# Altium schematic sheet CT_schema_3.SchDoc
size 229 x 200 mm
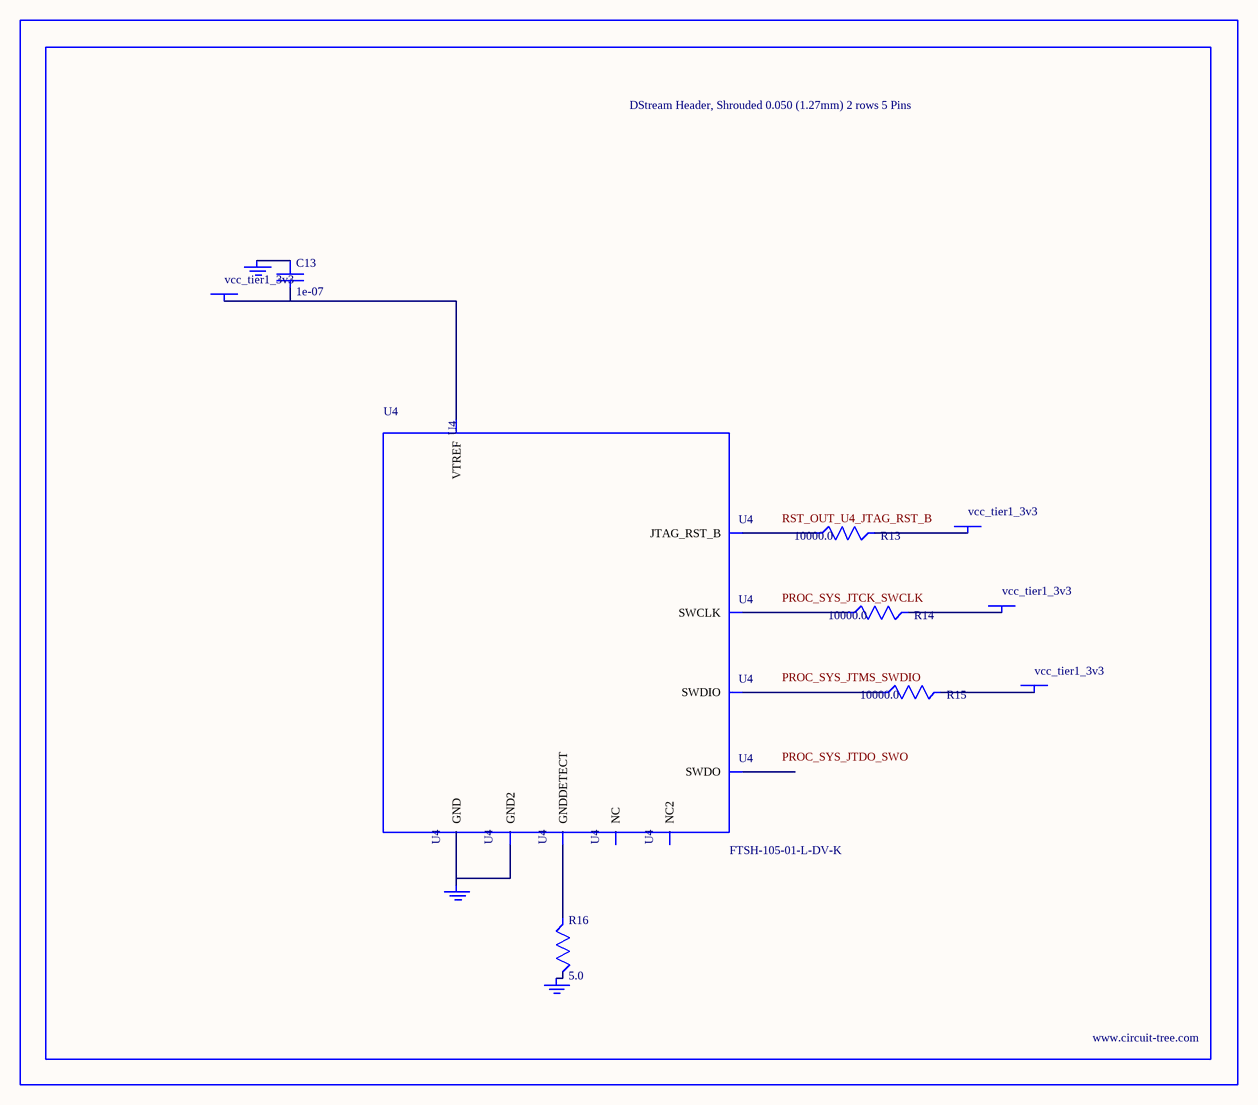
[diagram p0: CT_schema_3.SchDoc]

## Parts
BORDER2  (no value)
C13  1e-07  [C0402]
GND_INSTANCE_2_0  (no value)
GND_INSTANCE_2_1  (no value)
GND_INSTANCE_2_2  (no value)
POWER_INSTANCE_2_0  vcc_tier1_3v3
POWER_INSTANCE_2_1  vcc_tier1_3v3
POWER_INSTANCE_2_2  vcc_tier1_3v3
POWER_INSTANCE_2_3  vcc_tier1_3v3
R13  10000.0  [R0603]
R14  10000.0  [R0603]
R15  10000.0  [R0603]
R16  5.0  [R0603]
U4  FTSH-105-01-L-DV-K  [SAMTEC_FTSH-105-01-L-DV-K]

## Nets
NetC13_1: C13.1 GND_INSTANCE_2_0.0(GND)
NetC13_2: C13.2 POWER_INSTANCE_2_0.0(PWR) U4.1(VTREF)
NetGND_INSTANCE_2_1_0: GND_INSTANCE_2_1.0(GND) R16.2
NetGND_INSTANCE_2_2_0: GND_INSTANCE_2_2.0(GND) U4.3(GND) U4.5(GND2)
NetPOWER_INSTANCE_2_1_0: POWER_INSTANCE_2_1.0(PWR) R15.2
NetPOWER_INSTANCE_2_2_0: POWER_INSTANCE_2_2.0(PWR) R14.2
NetPOWER_INSTANCE_2_3_0: POWER_INSTANCE_2_3.0(PWR) R13.2
NetR13_1: R13.1 U4.10(JTAG_RST_B)
NetR14_1: R14.1 U4.4(SWCLK)
NetR15_1: R15.1 U4.2(SWDIO)
NetR16_1: R16.1 U4.9(GNDDETECT)

Not connected (* = marked no-connect by the designer): U4 6(SWDO) 7(NC) 8(NC2)

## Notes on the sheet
- Labels drawn without touching a wire or pin: PROC_SYS_JTCK_SWCLK, PROC_SYS_JTDO_SWO, PROC_SYS_JTMS_SWDIO, RST_OUT_U4_JTAG_RST_B

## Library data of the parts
BORDER2 = BORDER_PAGE2
C13 = C0402C104K3RACTU
GND_INSTANCE_2_0-GND_INSTANCE_2_2 = GND
POWER_INSTANCE_2_0-POWER_INSTANCE_2_3 = PWR
R13-R15 = RC0603JR-0710KL
R16 = ERJ-3GEYJ5R1V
